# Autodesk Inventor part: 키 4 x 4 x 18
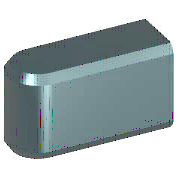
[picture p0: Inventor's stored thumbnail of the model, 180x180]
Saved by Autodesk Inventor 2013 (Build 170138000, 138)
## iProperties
IsCustomPart: 1
Created: 2012-02
Part Number: 키 4 x 4 x 18
Material: 강철, 연강
Description: 키 및 해당 키홈
Document SubType Name: Modeling
Standard: KS B 1311
Designer: mduedu
Standards Organization: KS
Language: ko-KR
Size Designation: 4 x 4 x 18
Categories: <MemberInstance><Categories><Category DisplayName="샤프트 부품" InternalName="7f7aeb1f-a693-4053-b835-cee3144e0d98" Mnemonic="SHFT"><Category DisplayName="키" Interna
Density: 1 g/cm^3
Author: mduedu
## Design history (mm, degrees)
sketch "스케치1"
  geometry: L1 (2, 2)-(18, 2); L2 (18, 2)-(18, -2); L3 (18, -2)-(2, -2); L4 (0, 7)-(0, -7) reference; L5 (-5, 0)-(30, 0) reference; A1 r 2 centre (2, 0) between (2, 2) and (2, -2)
  constraints: 6 end point, 3 tangent, 2 point on circle, 1 centre point, 1 horizontal, 1 parallel, 1 perpendicular, 1 point on line
  dimensions: "d0" = 2 radius of A1 (= 0.5 x PB); "d7" = 18 distance between parallel lines of L2 L4 (= NLG)
workplane "Work Plane1"
workplane "Work Plane2"
extrude "본체1" new body sketch "스케치1" taper "d3" = 0 deg; stored distance "d4" = 10
workaxis "Work Axis1"
workplane "Work Plane4"
body "Solid1"
chamfer "모따기1" distance "d8" = 0.25 (= PHH); stored, may be unused: second distance "d9" = 0.25 (= PHH), angle "d13" = 45 deg
other parameters: "d1" = -2.5 (= -PNT), "d2" = 1.5 (= PH - PNT), "NLG" = 18 [user parameter; used in 2 equation terms], "PB" = 4 [user parameter; used in 1 equation term], "PNT" = 2.5 [user parameter; used in 2 equation terms], "PH" = 4 [user parameter; used in 1 equation term], "PHH" = 0.25 [user parameter; used in 2 equation terms], "d10" = 0, "d16" = 0, "d17" = 0, "d18" = 0, "RR" = 0.08 [user parameter], "WDMAX" = 12 [user parameter], "PLB1" = 18 (= NLG) [user parameter], "PUEB" = 1.8 [user parameter]
